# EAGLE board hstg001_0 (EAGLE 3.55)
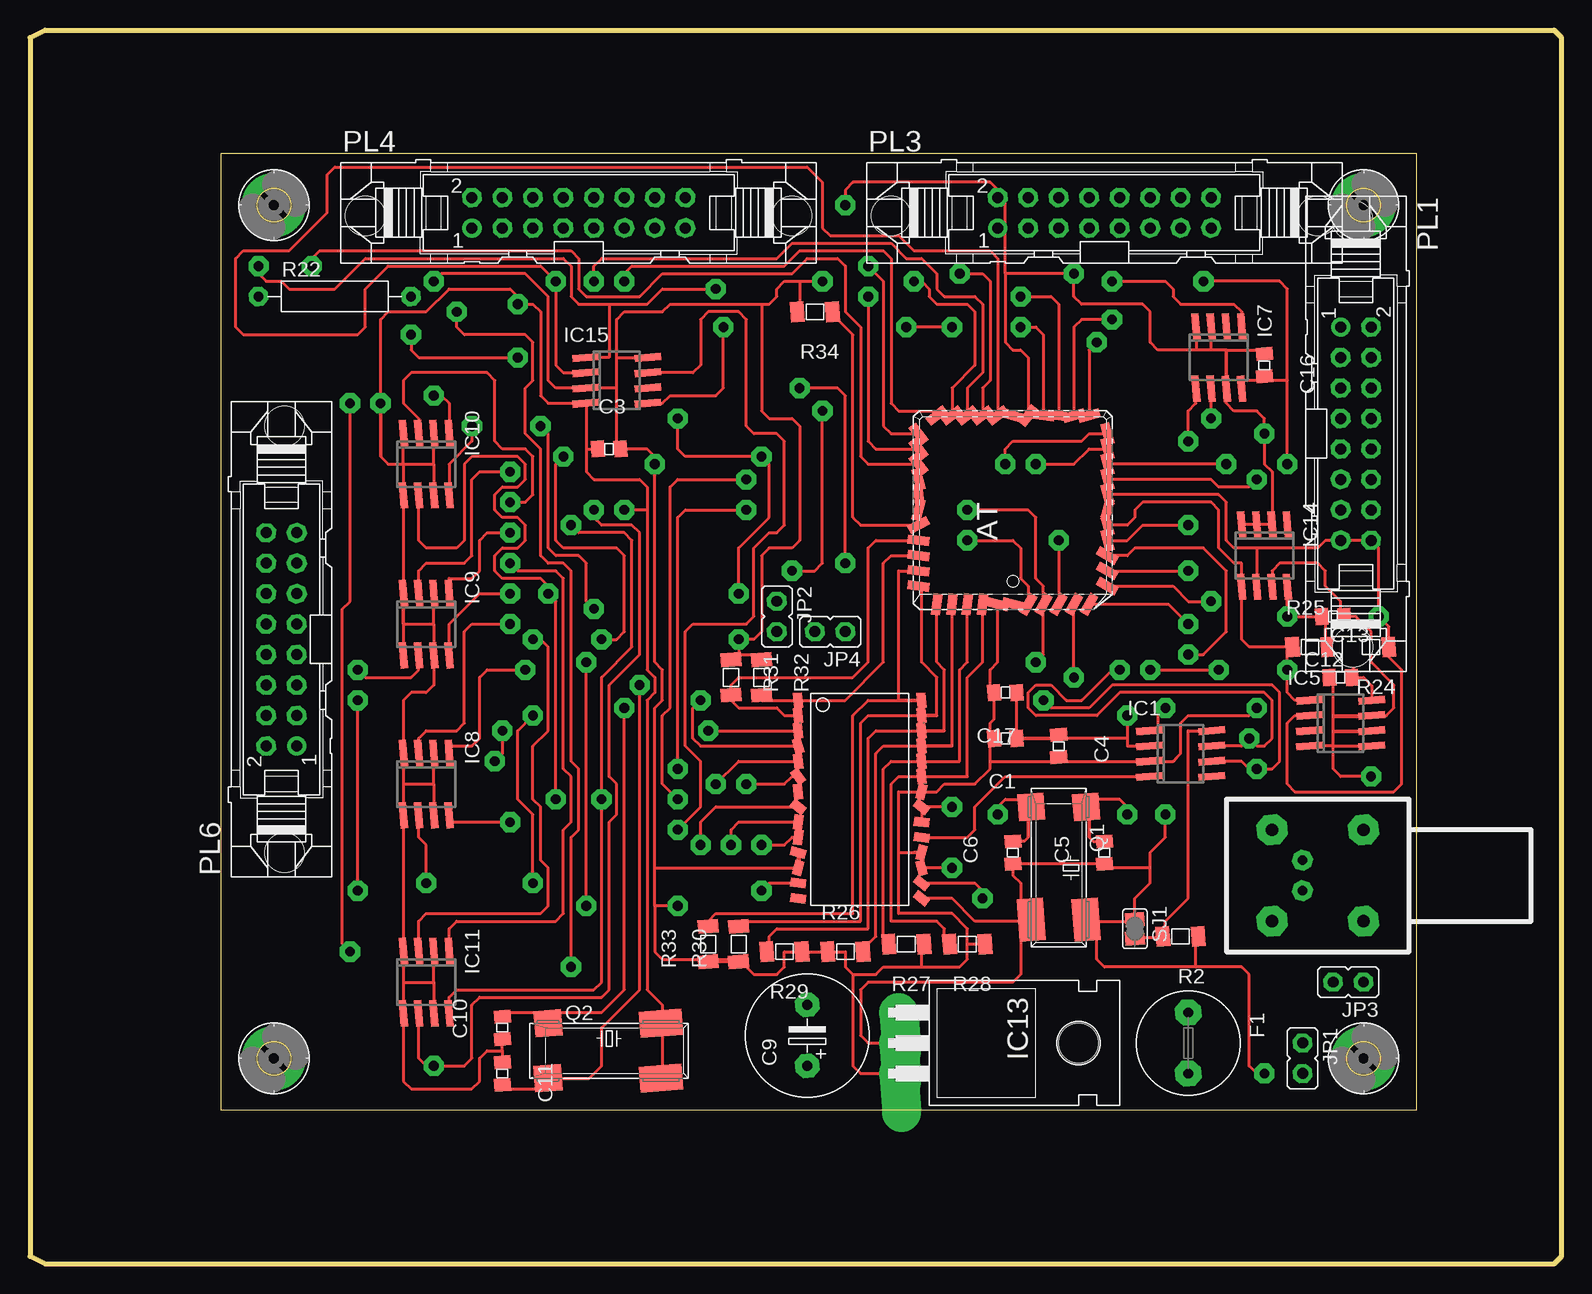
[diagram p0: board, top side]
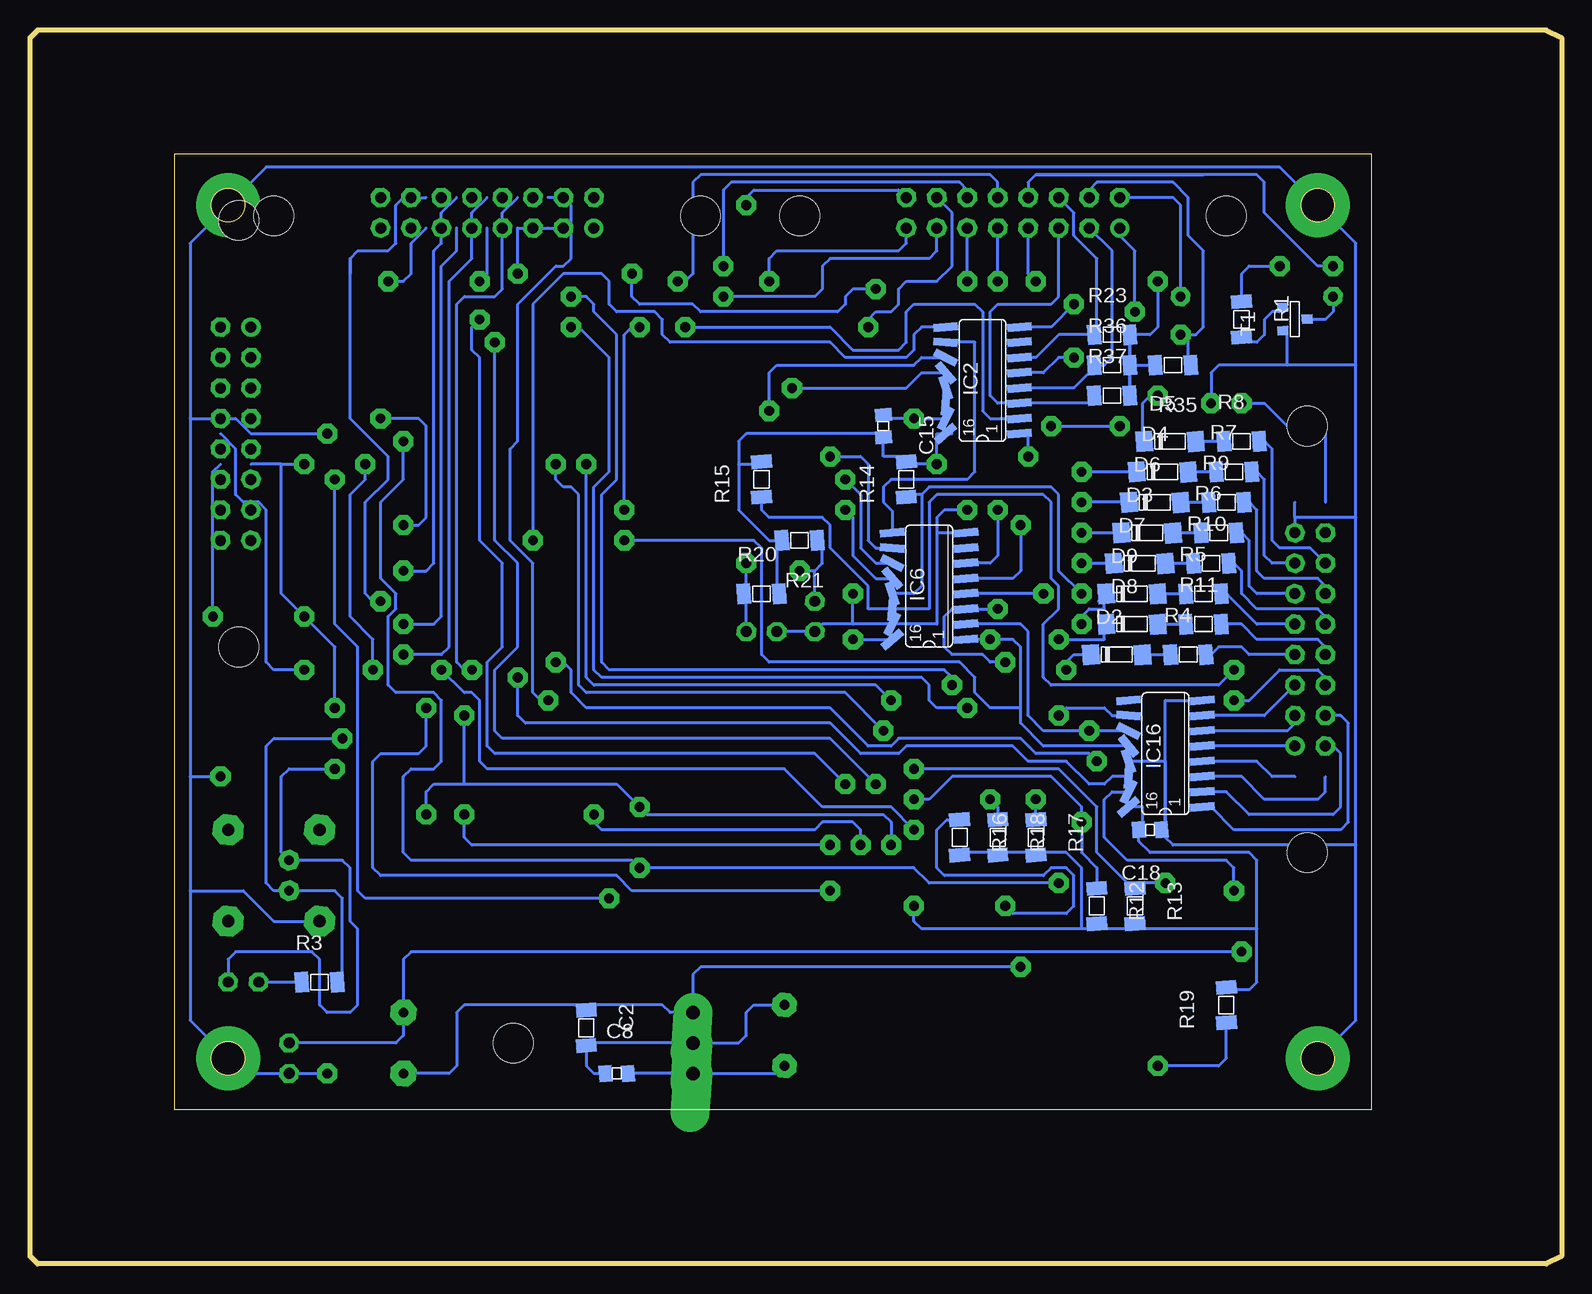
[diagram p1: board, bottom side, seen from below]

Size 127.64 x 102.87 mm. Coordinates in mm from the lower left corner, seen from the top.
Outline: 115.56,12.86 115.56,92.55 15.88,92.55 15.88,12.86 115.56,12.86
Outline: 0,0.63 1.27,0 127,0 127.64,0.63 127.64,102.23 127,102.87 1.27,102.87 0,102.23 0,0.63
Copper layers used: Top, Bottom
vRestrict: area 69.9,50.8 to 94,74.9

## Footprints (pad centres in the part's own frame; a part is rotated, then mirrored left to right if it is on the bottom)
05 = smd 1.092 x 1.397 rotated 4.4:  0.94,0 | smd 1.092 x 1.397 rotated 4.3:  -0.94,0
06 = smd 1.143 x 1.702 rotated 4.4:  1.473,0 | smd 1.143 x 1.702 rotated 4.3:  -1.473,0
-5 = drill 0.813 pad 2.007 octagon:  -2.54,0;  2.54,0
D-80 = smd 1.397 x 1.702 rotated 4.4:  -2.388,0 | smd 1.397 x 1.702 rotated 4.3:  1.905,-0.025
5 = drill 0.813 pad 2.159 octagon:  -2.54,0;  2.54,0
8 = smd 0.6 x 2.2 rotated 4.4:  -0.635,-2.6 | smd 0.6 x 2.2 rotated 4.8:  -0.635,2.6 | smd 0.6 x 2.2 rotated 4.3:  -1.905,-2.6 | smd 0.6 x 2.2 rotated 4.5:  0.635,-2.6 | smd 0.6 x 2.2 rotated 4.6:  1.905,-2.6 | smd 0.6 x 2.2 rotated 4.9:  -1.905,2.6 | smd 0.6 x 2.2 rotated 4.7:  0.635,2.6;  1.905,2.6
16 = smd 0.66 x 2.032 rotated 4.3:  -4.445,-3.073;  3.175,3.073 | smd 0.66 x 2.032 rotated 139.3:  -4.445,3.073 | smd 0.66 x 2.032 rotated 4.4:  -3.175,-3.073 | smd 0.66 x 2.032 rotated 4.5:  -1.905,-3.073 | smd 0.66 x 2.032 rotated 116.8:  -3.175,3.073 | smd 0.66 x 2.032 rotated 94.3:  -1.905,3.073 | smd 0.66 x 2.032 rotated 4.6:  -0.635,-3.073 | smd 0.66 x 2.032 rotated 71.8:  -0.635,3.073 | smd 0.66 x 2.032 rotated 4.7:  0.635,-3.073;  1.905,-3.073 | smd 0.66 x 2.032 rotated 49.3:  0.635,3.073 | smd 0.66 x 2.032 rotated 4.8:  3.175,-3.073 | smd 0.66 x 2.032 rotated 26.8:  1.905,3.073 | smd 0.66 x 2.032 rotated 4.9:  4.445,-3.073 | smd 0.66 x 2.032 rotated 5:  4.445,3.073
CC-44 = smd 0.76 x 1.8 rotated 74.5: 0 -1.27,-7.86; 1 1.27,-7.86; 2 2.54,-7.86; 3 3.81,-7.86; 4 5.08,-7.86; 5 6.35,-7.86; N 2.54,7.86 | smd 1.8 x 0.76 rotated 29.5: 0 -7.86,-1.27; 1 -7.86,-2.54; 2 -7.86,-3.81; 3 -7.86,-5.08; 4 -7.86,-6.35 | smd 1.8 x 0.76 rotated 7: 0 -7.86,2.54; 1 -7.86,3.81; 2 -7.86,5.08; 3 -7.86,6.35 | smd 1.8 x 0.76 rotated 52: 0 7.86,1.27; 1 7.86,2.54; 2 7.86,3.81; 3 7.86,5.08; 4 7.86,6.35 | smd 0.76 x 1.8 rotated 7: 4 -6.35,7.86; 5 -5.08,7.86; 6 -3.81,7.86; 7 -2.54,7.86 | smd 0.76 x 1.8 rotated 52: 5 6.35,7.86; 6 5.08,7.86; 7 3.81,7.86 | smd 0.76 x 1.8 rotated 29.5: 5 -6.35,-7.86; 6 -5.08,-7.86; 7 -3.81,-7.86 | smd 1.8 x 0.76 rotated 74.5: 6 7.86,-6.35; 7 7.86,-5.08 | smd 0.76 x 1.8 rotated 275.7: /PR 1.27,7.86 | smd 1.8 x 0.76 rotated 97.7: L1 7.86,-2.54; L2 7.86,-3.81 | smd 0.76 x 1.8 rotated 28.6: VPP -1.27,7.86 | smd 0.76 x 1.8 rotated 74.7:  -2.54,-7.86 | smd 0.76 x 1.8 rotated 74.4:  0,-7.86;  0,7.86 | smd 1.8 x 0.76 rotated 74.4:  -7.86,0;  7.86,0 | smd 1.8 x 0.76 rotated 75.1:  -7.86,1.27 | smd 1.8 x 0.76 rotated 321.2:  7.86,-1.27
-28L = smd 0.762 x 1.27 rotated 321.2: 1 1.27,-5.207; 2 1.27,5.08; 3 8.89,5.08 | smd 0.762 x 1.27 rotated 75.1: 1 0,5.08; 2 5.08,5.08; 3 6.35,-5.207 | smd 0.762 x 1.27 rotated 74.7: / 6.35,5.08 | smd 0.762 x 1.27 rotated 321.4: / 7.62,5.08 | smd 0.762 x 1.27 rotated 275.7: /AS -5.08,-5.207 | smd 0.762 x 1.27 rotated 97.2: E -2.54,-5.207 | smd 0.762 x 1.27 rotated 344.3: E 5.08,-5.207 | smd 0.762 x 1.27 rotated 97.7: L1 2.54,-5.207; L2 3.81,-5.207 | smd 0.762 x 1.27 rotated 275.9: OUT 0,-5.207 | smd 0.762 x 1.27 rotated 95.7:  -7.62,-5.207;  -6.35,-5.207;  -1.27,5.08;  -2.54,5.08;  -3.81,5.08;  -5.08,5.08;  -6.35,5.08;  -7.62,5.08 | smd 0.762 x 1.27 rotated 73.4:  -3.81,-5.207 | smd 0.762 x 1.27 rotated 52.6:  -1.27,-5.207 | smd 0.762 x 1.27 rotated 187.2:  2.54,5.08;  3.81,5.08 | smd 0.762 x 1.27 rotated 187.4:  8.89,-5.207;  7.62,-5.207
220H = drill 1.118 pad 3.251 offset:  -2.54,-10.16;  0,-10.16;  2.54,-10.16 | hole 3.302: 0,4.826
1 = drill 0.914 pad 1.6 octagon:  0,-1.27;  0,1.27
2,8-P = drill 2.794 pad 5.334 round: 8 0,0
V = drill 0.914 pad 1.6 round:  -8.89,-1.27 | drill 0.914 pad 1.6 octagon:  -8.89,1.27;  -6.35,-1.27;  -6.35,1.27;  -3.81,-1.27;  -3.81,1.27;  -1.27,-1.27;  -1.27,1.27;  1.27,-1.27;  1.27,1.27;  3.81,-1.27;  3.81,1.27;  6.35,-1.27;  6.35,1.27;  8.89,-1.27;  8.89,1.27 | hole 3.302: 17.78,-0.254; -17.78,-0.254
N_EPL = drill 1.016 pad 2.54 octagon: 1 -3.81,3.81; 2 3.81,3.81; 3 -3.81,-3.81; 4 3.81,-3.81 | drill 0.813 pad 1.676 octagon: H -1.27,1.27; L 1.27,1.27
SMX = smd 3.556 x 2.184 rotated 4.4:  4.318,-2.286 | smd 3.556 x 2.184 rotated 4.5:  4.318,2.286 | smd 2.286 x 2.184 rotated 4.3:  -5.08,-2.286 | smd 2.286 x 2.184 rotated 4.6:  -5.08,2.286
12,5 = drill 0.813 pad 1.6 octagon:  -6.35,0;  6.35,0
 = smd 1.168 x 1.6 rotated 4.3:  -0.762,0 | smd 1.168 x 1.6 rotated 4.4:  0.762,0
T-23 = smd 0.787 x 0.889 rotated 4.4:  0.991,1.016 | smd 0.787 x 0.889 rotated 4.3:  -0.94,1.016 | smd 0.787 x 0.889 rotated 4.5:  0.025,-1.016

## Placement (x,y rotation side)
C1  100n  [05]  81.28,43.81 180 top
C2  330n  [06]  81.28,19.68 270 bottom
C3  100n  [05]  48.26,67.94 0 top
C4  100n  [05]  85.72,43.18 270 top
C5  15pF  [05]  89.53,34.29 90 top
C6  15pF  [05]  81.92,34.29 90 top
C8  100n  [05]  78.74,15.88 0 bottom
C9  Elko 470uF  [-5]  64.77,19.05 90 top
C10  30pF +-10pF  [05]  39.37,19.68 90 top
C11  30 pF+-10pF  [05]  39.37,15.88 270 top
C12  100n  [05]  108.58,53.97 180 top
C13  100n  [05]  109.22,48.89 0 top
C15  100n  [05]  56.52,69.85 270 bottom
C16  100n  [05]  102.87,74.93 270 top
C17  100n  [05]  81.28,47.62 180 top
C18  100n  [05]  34.29,36.2 180 bottom
D2  SMD4148  [D-80]  36.83,50.8 0 bottom
D3  SMD4148  [D-80]  34.29,60.96 0 bottom
D4  SMD4148  [D-80]  33.02,66.04 0 bottom
D5  SMD4148  [D-80]  32.39,68.58 0 bottom
D6  SMD4148  [D-80]  33.66,63.5 0 bottom
D7  SMD4148  [D-80]  34.92,58.42 0 bottom
D8  SMD4148  [D-80]  35.56,53.34 0 bottom
D9  SMD4148  [D-80]  35.56,55.88 0 bottom
F1  T200mA  [5]  96.52,18.41 270 top
IC1  PCA82C250  [8]  95.89,42.55 270 top
IC2  74165  [16]  48.26,73.66 90 bottom
IC3  AT89S53  [CC-44]  81.92,62.86 90 top
IC4  SJA1000  [-28L]  69.22,39.37 270 top
IC5  DS1621  [8]  109.22,45.08 270 top
IC6  74165  [16]  52.7,56.52 90 bottom
IC7  MAX700  [8]  99.06,75.56 180 top
IC8  ILD213T  [8]  33.02,40 180 top
IC9  ILD213T  [8]  33.02,53.34 180 top
IC10  ILD213T  [8]  33.02,66.67 180 top
IC11  ILD213T  [8]  33.02,23.49 180 top
IC13  78S05  [220H]  82.55,18.41 270 top
IC14  X24C04  [8]  102.87,59.05 180 top
IC15  DS1804  [8]  48.9,73.66 270 top
IC16  74HC595  [16]  33.02,42.55 90 bottom
JP1  2-polig  [1]  106.05,17.14 180 top
JP2  JP1E  [1]  62.23,53.97 180 top
JP3  2-polig  [1]  109.86,23.49 90 top
JP4  JP1E  [1]  66.67,52.7 90 top
PAD1  BO2,8P  [2,8-P]  20.32,88.27 0 top
PAD2  BO2,8P  [2,8-P]  20.32,17.14 0 top
PAD3  BO2,8P  [2,8-P]  111.12,17.14 0 top
PAD4  BO2,8P  [2,8-P]  111.12,88.27 0 top
PL1  06V  [V]  110.49,69.22 270 top
PL2  CAN_BUS  [N_EPL]  107.31,32.38 90 top
PL3  10V  [V]  89.53,87.63 0 top
PL4  16V  [V]  45.72,87.63 0 top
PL6  20V  [V]  20.95,52.07 90 top
Q1  16MHZ  [SMX]  85.72,33.02 270 top
Q2  16MHZ  [SMX]  48.26,17.78 0 top
R1  4k7  [06]  26.67,78.74 270 bottom
R2  47k  [06]  95.89,27.3 180 top
R3  120R  [06]  103.5,23.49 0 bottom
R4  2k7  [06]  31.12,50.8 0 bottom
R5  2k7  [06]  29.84,55.88 0 bottom
R6  2k7  [06]  28.57,60.96 0 bottom
R7  2k7  [06]  27.3,66.04 0 bottom
R8  2k7  [06]  26.67,68.58 0 bottom
R9  2k7  [06]  27.94,63.5 0 bottom
R10  2k7  [06]  29.21,58.42 0 bottom
R11  2k7  [06]  29.84,53.34 0 bottom
R12  4k7  [06]  38.73,29.84 270 bottom
R13  4k7  [06]  35.56,29.84 270 bottom
R14  4k7  [06]  54.61,65.41 90 bottom
R15  4k7  [06]  66.67,65.41 90 bottom
R16  4k7  [06]  50.16,35.56 270 bottom
R17  4k7  [06]  43.81,35.56 270 bottom
R18  4k7  [06]  46.99,35.56 270 bottom
R19  4k7  [06]  27.94,21.59 90 bottom
R20  10k  [06]  66.67,55.88 0 bottom
R21  10k  [06]  63.5,60.33 180 bottom
R22  100 Ohm  [12,5]  25.4,80.64 0 top
R23  10 k  [06]  37.47,77.47 0 bottom
R24  1k  [06]  111.76,51.44 180 top
R25  1k  [06]  106.68,51.44 0 top
R26  4k7  [06]  67.94,26.04 0 top
R27  4k7  [06]  73.03,26.67 180 top
R28  4k7  [06]  78.1,26.67 180 top
R29  4k7  [06]  62.87,26.04 180 top
R30  4k7  [06]  59.05,26.67 90 top
R31  4k7  [06]  58.42,48.89 270 top
R32  4k7  [06]  60.96,48.89 270 top
R33  4k7  [06]  56.52,26.67 90 top
R34  4k7  [06]  65.41,79.38 180 top
R35  10 k  [06]  32.39,74.93 180 bottom
R36  10 k  [06]  37.47,74.93 0 bottom
R37  10 k  [06]  37.47,72.39 0 bottom
SJ1  SJ  []  92.08,27.94 270 top
T1  BC818  [T-23]  22.23,78.74 90 bottom

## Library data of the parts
C1-C6 C8 C10-C13 C15-C18 D2-D9 R1-R21 R23-R37 T1 = smd
C9 R22 = discrete
F1 = fuse
IC1 IC3-IC5 IC7-IC11 IC14 IC15 PL2 = andit4at
IC2 IC6 IC16 = andi74sm
IC13 = linear
JP1-JP4 = jumps
PAD1-PAD4 = holes
PL1 PL3 PL4 PL6 = pinh-v
Q1 Q2 = quartz
SJ1 = jumper

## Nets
+5V: C1. C3. C4. C8. C9. C12. C13. C15. C16. C17. C18. IC1. IC2. IC3. IC4.1 IC4.2 IC4.3 IC4.E IC5. IC6. IC7. IC13. IC14. IC15. IC16. PL1. PL3. PL4. R12. R13. R14. R15. R16. R17. R18. R19. R20. R21. R23. R24. R25. R26. R27. R28. R29. R30. R31. R32. R33. R34. R35. R36. R37.
GND: C1. C2. C3. C4. C5. C6. C8. C9. C10. C11. C12. C13. C15. C16. C17. C18. IC1. IC2. IC3. IC4. IC4.1 IC4.2 IC4.3 IC5. IC6. IC7. IC8. IC9. IC10. IC11. IC13. IC14. IC15. IC16. JP1. JP2. JP4. PAD1.8 PAD2.8 PAD3.8 PAD4.8 PL1. PL2.1 PL3. PL4. PL6. Q1. Q2. R2. SJ1. T1.
N$1: IC3.0 IC4. R28.
N$2: IC3.1 IC4. R27.
N$3: IC3.5 IC4. R33.
N$4: IC3.VPP R34.
N$5: IC3.7 IC4. R31.
N$6: PL4. R22.
N$9: IC1. IC4.
N$10: IC2. IC3.1 IC6. IC16.
N$11: C11. IC3.L2 Q2.
N$12: IC2. IC3.2
N$13: IC3.0 IC15. PL4.
N$15: IC16. PL6.
N$16: IC1. PL2.H PL3. R3.
N$17: IC15. PL4.
N$18: PL6. R11.
N$19: IC2. PL4. R35.
N$20: IC2. PL4. R37.
N$21: PL6. R10.
N$22: IC2. PL4. R36.
N$23: C2. F1. IC13. PL4.
N$24: IC2. IC6.
N$26: PL6. R9.
N$27: D9. R5.
N$28: D2. R4.
N$29: IC2. IC3.0 IC6. IC16.
N$31: D3. R6.
N$32: D4. R7.
N$33: D5. R8.
N$35: D6. R9.
N$36: IC1. JP3. PL2.L PL3.
N$37: IC3.4 IC4./AS
N$38: IC3.6 PL3.
N$39: IC3.5 PL3.
N$40: IC3.7 PL3.
N$41: IC3. IC7.
N$42: IC3.5 IC4.
N$43: IC16. PL6.
N$44: IC3.1 IC5. IC14. PL1. R24.
N$45: IC3.0 IC5. IC14. PL1. R25.
N$46: IC3.6 IC4.E
N$47: IC3.7 IC4.
N$48: IC3.2 IC4./
N$49: IC7. PL3.
N$50: IC4./ IC7. IC16.
N$51: C5. IC4.L2 Q1.
N$52: C6. IC4.L1 Q1.
N$53: R22. T1.
N$54: IC3.2 PL4.
N$55: IC1. IC4.
N$56: IC3.3 PL4.
N$57: IC3.5 PL4.
N$58: IC3.6 PL4.
N$59: IC3.4 PL4.
N$60: IC3.7 R1.
N$61: F1. JP1. PL6.
N$63: IC1. R2. SJ1.
N$64: D7. R10.
N$65: JP3. R3.
N$67: D8. R11.
N$68: D9. IC8.
N$70: C10. IC3.L1 Q2.
N$71: D3. IC9.
N$72: D4. IC9.
N$73: D5. IC10.
N$74: D6. IC10.
N$75: D7. IC11.
N$76: IC6. IC8. R12.
N$77: D8. IC11.
N$78: IC2. PL4. R23.
N$79: IC3.4 PL3.
N$80: IC6. IC8. R13.
N$81: R1. T1.
N$82: D2. IC8.
N$83: IC6. IC9. R14.
N$85: IC6. IC9. R15.
N$87: IC6. IC10. R16.
N$89: IC6. IC10. R17.
N$90: IC16. PL6.
N$91: IC6. IC11. R18.
N$92: IC16. PL6.
N$93: IC6. IC11. R19.
N$94: IC16. PL6.
N$95: IC16. PL6.
N$96: IC3.3 IC15.
N$97: IC16. PL6.
N$98: IC3.3 IC16.
N$99: IC16. PL6.
N$100: IC2. JP4. R20.
N$101: IC2. JP2. R21.
N$102: IC3.2 IC4. R26.
N$104: IC3.3 IC4. R29.
N$105: IC3.4 IC4. R30.
N$106: IC3.6 IC4. R32.
N$107: IC3.1 IC15. PL4.
N$108: PL6. R8.
N$109: PL6. R4.
N$110: PL6. R5.
N$111: PL6. R6.
N$112: PL6. R7.

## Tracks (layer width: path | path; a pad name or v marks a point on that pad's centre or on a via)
+5V  (via drill 0.81 pad 1.68)
  Top 0.254: v97.79,81.92 104.14,81.92 104.78,81.28 104.78,73.66 | 73.66,34.29 74.3,34.29 72.39,34.29 | 64.13,33.15 IC4.3 | 64.13,33.15 64.13,34.29 | 72.39,34.29 72.39,39.37 IC4.1 75.56,39.37 76.2,40 78.74,40 80.01,41.27 80.01,41.91 | 72.39,34.29 72.39,29.21 76.84,29.21 78.1,27.94 78.1,26.67 | IC4.E 64.01,33.15 64.13,33.02 | 52.07,33.02 64.13,33.02 | 80.64,55 80.64,50.17 80.01,49.53 80.01,47.62 80.34,47.62 80.34,45.42 80.01,45.08 80.01,43.81 | 102.87,74.3 102.87,73.99 102.87,73.66 | 64.13,33.02 64.13,33.15 | 110.49,48.89 110.29,49.1 110.29,51.44 108.15,51.44 107.95,51.44 107.95,53.97 107.64,53.97 v104.78,53.97 104.78,56.45 | 111.82,46.99 111.82,48.2 111.12,48.89 110.49,48.89 | 110.49,48.89 110.16,48.89 | v104.78,66.67 104.78,73.66 | 104.78,73.66 102.87,73.66 | 100.97,72.97 100.97,73.66 102.87,73.66 | 95.25,41.91 95.56,42.22 | 85.72,41.91 93.28,41.91 95.25,41.91 | 95.25,41.91 95.89,42.55 95.89,45.08 96.52,45.72 101.6,45.72 v102.23,46.36 | 78.1,26.67 R28. | R26. 66.04,26.04 | R26. 67.94,26.04 67.94,24.77 68.58,24.13 | R26. R29. 62.87,26.04 62.87,24.77 62.23,24.13 60.33,24.13 59.69,24.77 | R33. 58.85,25.2 59.05,25.4 R30. 59.26,25.2 59.69,24.77 | 80.01,43.81 80.34,43.81 | 80.01,41.91 80.01,43.81 | 85.72,41.91 85.72,42.24 | 80.01,41.91 85.72,41.91 | 59.69,24.77 59.69,25.4 52.7,25.4 52.07,26.04 52.07,29.84 | 52.07,29.84 52.07,33.02 | 68.58,24.13 68.58,16.51 69.22,15.88 IC13. | 68.58,24.13 70.48,24.13 71.12,24.77 74.3,24.77 | 74.93,26.67 R27. 74.3,26.67 74.3,24.77 | 74.3,24.77 77.47,24.77 78.1,25.4 78.1,26.67 | 48.9,73.03 46.3,73.03 43.81,73.03 43.18,73.66 43.18,80.64 41.27,82.55 34.29,82.55 v33.66,81.92
  Top 0.254: 48.9,73.03 48.9,75.56 | 48.9,75.56 51.49,75.56 | 48.9,75.56 48.9,78.74 49.53,79.38 52.7,79.38 53.34,80.01 60.96,80.01 | 52.07,33.02 52.07,46.36 52.7,46.99 52.7,49.53 52.07,50.17 v52.07,66.67 52.07,67.31 51.44,67.94 49.53,67.94 | R31. 58.42,50.17 58.62,50.37 58.62,50.6 58.42,50.8 59.05,50.8 | R32. 60.96,50.17 60.33,50.8 59.05,50.8 | 64.13,81.92 62.87,81.92 62.23,81.28 62.23,80.64 61.59,80.01 60.96,80.01 | 64.13,81.92 v66.04,81.92 | 63.93,79.38 64.13,79.38 64.13,81.92 | v53.98,29.84 52.07,29.84 | 49.53,67.94 49.2,67.94 | 48.9,73.03 48.9,68.58 49.53,67.94 | 59.05,50.8 v59.05,52.07 60.33,52.07 60.96,52.7 60.96,59.05 61.59,59.69 63.5,59.69 64.13,60.33 64.13,69.85 63.5,70.48 61.59,70.48 60.96,71.12 60.96,80.01
  Bottom 0.254: 94.61,86.36 95.89,85.09 95.89,82.55 96.52,81.92 v97.79,81.92 | 106.68,66.67 109.22,66.67 | 106.68,66.67 v104.78,66.67 | 106.68,66.67 106.68,55.88 v104.78,53.97 102.23,51.44 v102.23,46.36 | 77.8,15.88 IC13. 65.41,15.88 64.77,16.51 | 36.2,38.1 36.09,38.1 34.92,38.1 34.92,36.2 35.23,36.2 35.23,35.23 34.29,34.29 26.04,34.29 25.4,33.66 25.4,27.94 | 54.61,86.36 54.61,85.09 55.24,84.45 65.41,84.45 66.04,83.82 v66.04,81.92 | 66.67,66.67 66.67,66.88 | 66.67,66.67 66.88,66.88 | 36.2,74.93 35.76,75.36 | 35.99,74.93 36.2,74.93 | 35.99,77.47 35.99,75.13 36.2,74.93 | 35.99,72.39 36.2,72.39 35.99,72.59 | 35.99,72.59 35.99,74.93 | 33.66,74.93 33.86,74.93 35.99,74.93 | 35.99,72.59 35.99,77.04 35.56,77.47 34.29,77.47 33.66,78.11 v33.66,81.92 | 50.8,69.22 51.33,69.22 52.07,69.22 v52.07,66.67 54.61,66.67 54.61,66.88 54.61,67.31 56.52,67.31 | 68.58,66.67 66.67,66.67 | 64.77,60.33 64.97,60.33 65.41,60.33 | 56.52,67.31 56.52,68.91 | 40,27.94 53.34,27.94 53.98,28.57 v53.98,29.84 | 40,27.94 40,33.02 41.27,34.29 43.81,34.29 | 35.56,27.94 35.56,28.37 | 35.56,27.94 38.73,27.94 | 38.73,27.94 38.73,28.37 | 38.73,27.94 40,27.94 | 65.2,55.88 65.41,55.88 65.41,60.33 | 65.41,60.33 66.04,60.33 68.58,62.86 68.58,66.67 | 68.58,66.67 68.58,68.58 67.94,69.22 56.52,69.22 56.52,67.31 | 25.4,27.94 35.56,27.94 | 25.4,27.94 25.4,23.49 26.04,22.86 27.94,22.86 27.94,23.06 | 43.81,34.29 43.81,34.09 | 43.81,34.29 46.99,34.29 | 46.99,33.66 46.99,34.09 46.99,34.29 | 50.16,34.09 50.16,34.29 46.99,34.29 | v59.05,52.07 55.78,52.07 v59.05,52.07
GND  (via drill 0.81 pad 1.68)
  Top 0.254: 97.16,78.17 97.22,78.11 97.22,76.26 97.16,76.2 | 99.69,76.2 102.54,76.2 | 99.69,76.2 98.42,76.2 | 99.69,76.2 99.69,72.97 | 97.16,76.2 93.98,76.2 93.34,76.84 93.34,79.38 92.71,80.01 87.63,80.01 87,80.64 v87,82.55 81.28,82.55 | 83.19,70.72 83.19,75.56 82.55,76.2 81.92,76.2 81.28,76.84 81.28,82.55 | 111.76,44.45 111.82,44.39 108.64,44.39 108.58,44.45 | 111.76,45.72 111.82,45.66 108.64,45.66 108.58,45.72 | 111.76,43.18 111.82,43.24 | 108.58,43.18 106.62,43.18 | 108.58,45.72 111.76,45.72 | C13. 107.95,48.89 108.58,48.26 108.58,45.72 | 100.97,61.66 102.17,61.66 102.23,61.59 102.23,61.66 103.44,61.66 103.5,61.59 | 111.76,45.72 111.82,45.72 | 111.76,45.72 113.03,45.72 113.67,46.36 113.67,48.26 111.76,50.17 111.76,52.7 110.49,53.97 C12. 109.22,53.97 109.22,55.25 107.95,56.52 107.95,57.78 107.31,58.42 104.14,58.42 103.5,57.78 103.5,56.45 | IC4.2 v76.84,38.1 IC4.2 | 99.69,76.2 102.87,76.2 C16. 102.87,75.56 | 99.69,76.2 99.69,71.75 100.33,71.12 102.23,71.12 102.87,70.48 v102.87,69.22 102.87,66.67 103.5,66.04 103.5,61.59 | 103.5,61.59 103.5,61.66 | 98.42,76.2 97.16,76.2 | 98.42,76.2 98.42,78.17 | 108.58,44.45 108.58,45.72 | 111.76,44.45 111.82,44.45 | 108.58,44.45 111.76,44.45 | 108.58,43.18 108.58,44.45 | 111.76,43.18 IC5. | 108.58,43.18 111.76,43.18 | 108.58,43.18 108.58,41.27 109.22,40.64 v111.76,40.64 | 89.53,33.02 C5. | 89.53,33.02 89.2,33.35 C6. 81.92,32.38 82.55,31.75 82.55,28.57 | 89.53,33.66 89.84,33.35 | 89.53,33.66 89.53,33.02 | v94.61,37.47 94.61,35.56 93.34,34.29 93.34,33.02 | 93.34,33.02 90.17,33.02 89.53,33.66 | 93.34,33.02 93.34,31.75 92.08,30.48 92.08,28.7 92.08,28.57 88.9,28.57
  Top 0.254: 88.9,28.57 88.9,25.4 89.53,24.77 97.16,24.77 | R2. 97.16,27.3 97.16,24.77 | 91.44,43.81 C1. | C4. 85.72,44.45 85.09,43.81 C1. | 93.28,43.18 91.44,43.18 91.44,43.81 | 31.12,66.67 31.12,69.28 | 31.12,66.67 IC10. | 29.84,66.67 31.12,66.67 | v29.21,71.75 29.21,67.31 | 31.12,53.34 31.12,55.94 | 33.66,53.34 33.66,50.74 | 33.66,66.67 33.66,64.08 | 31.12,66.67 33.66,66.67 | 31.12,66.67 31.12,53.34 | 33.66,53.34 33.66,55.94 | v91.44,45.72 91.44,43.81 | 97.16,24.77 100.97,24.77 101.6,24.13 101.6,16.51 102.23,15.88 v102.87,15.88 | 74.3,30.48 76.84,30.48 78.74,28.57 82.55,28.57 | 82.55,28.57 82.55,24.13 81.92,23.49 69.85,23.49 69.22,22.86 69.22,19.05 69.85,18.41 72.39,18.41 | 46.36,71.75 46.3,71.75 43.18,71.75 | v67.94,88.27 67.94,89.53 68.58,90.17 80.01,90.17 81.28,88.9 81.28,82.55 | 33.66,53.34 33.66,48.26 33.02,47.62 31.75,47.62 31.12,46.99 31.12,42.55 | 31.12,53.34 33.66,53.34 | 31.12,53.34 IC9. | C17. 81.92,47.62 82.22,47.32 C1. | IC4.2 74.3,36.83 | IC4.2 74.3,36.83 | IC4.2 74.3,36.83 | 83.44,28.7 83.31,28.7 83.19,28.57 82.55,28.57 | 88.01,28.7 88.14,28.7 88.27,28.57 88.9,28.57 | 64.01,38.1 57.15,38.1 55.88,36.83 v55.88,34.92 | 31.12,42.55 31.12,40 | 31.12,42.55 31.12,42.61 | 33.66,40 33.66,42.61 | 31.12,40 31.12,37.47 | 31.12,37.47 IC8. | 31.12,40 33.66,40 | 31.12,26.04 31.12,26.09 | 31.12,23.49 31.12,20.95 | 33.66,23.49 33.66,20.89 | 33.66,23.49 33.66,26.09 | 31.12,23.49 33.66,23.49 | 31.12,26.04 31.12,23.49 | 31.12,37.47 31.12,26.04 | 33.66,40 33.66,37.41 33.66,36.83 | 43.18,71.75 42.55,72.39 42.55,79.38 41.91,80.01 v40.64,80.01 40.64,80.64 40,81.28 34.92,81.28 33.02,79.38 29.84,79.38 29.21,78.74 29.21,67.31 | 43.18,71.75 46.36,71.75
  Top 0.254: 31.12,20.95 IC11. | 31.12,20.95 31.12,15.24 31.75,14.6 36.83,14.6 37.47,15.24 37.47,17.14 38.1,17.78 39.37,17.78 | v59.05,55.88 59.05,59.69 61.59,62.23 61.59,66.67 v60.96,67.31 54.61,67.31 53.98,67.94 v53.98,70.48 | 52.7,19.68 52.7,20.32 52.58,20.19 52.58,20.07 52.58,19.81 52.7,19.68 | 52.7,19.68 52.7,21.59 51.44,22.86 51.44,46.99 52.07,47.62 52.07,48.89 51.44,49.53 51.44,62.86 | 39.37,16.51 C11. 39.37,17.78 | 39.37,17.78 C10. | 52.58,15.49 52.58,15.37 52.7,15.24 52.7,19.68 | 46.36,71.75 46.36,67.94 | 46.36,67.94 46.36,66.04 46.99,65.41 50.8,65.41 51.44,64.77 51.44,62.86 | 46.36,67.94 C3. | 33.66,66.67 33.66,69.28 | 29.84,66.67 33.66,66.67 | 29.21,67.31 29.84,66.67 | 51.44,62.86 v49.53,62.86
  Bottom 0.254: 114.3,70.48 114.3,85.09 PAD4.8 107.95,91.44 23.5,91.44 PAD1.8 17.14,85.09 17.14,74.93 | 114.3,70.48 114.3,40.64 | 114.3,40.64 114.3,31.11 | 114.3,31.11 114.3,20.32 PAD3.8 109.86,15.88 JP1. v102.87,15.88 | PAD2.8 17.14,20.32 17.14,34.92 | 83.82,86.36 84.45,86.36 87,86.36 v87,82.55 | PL2.1 107.31,28.57 109.86,31.11 114.3,31.11 | 114.3,40.64 v111.76,40.64 | 109.22,69.22 v102.87,69.22 109.22,69.22 | 91.44,40 78.74,40 v76.84,38.1 76.2,37.47 56.52,37.47 55.88,36.83 v55.88,34.92 | v94.61,37.47 94.61,39.37 93.98,40 91.44,40 | C8. 80.64,15.88 81.28,16.51 81.28,18.21 81.28,18.41 72.39,18.41 68.58,18.41 67.94,19.05 67.94,20.95 67.31,21.59 C9. | 22.23,62.23 22.23,60.96 | 33.02,41.91 33.02,46.99 29.95,46.99 | 36.2,41.91 36.09,41.91 33.02,41.91 | JP4. JP2. 61.59,53.34 59.05,53.34 | 49.53,60.96 49.63,60.96 52.07,60.96 | 91.44,40 v91.44,45.72 | 52.07,60.96 52.07,53.34 55.78,53.34 59.05,53.34 | 44.45,78.11 45.19,78.11 42.55,78.11 v40.64,80.01 | PL4. 55.24,89.53 67.31,89.53 67.94,88.9 v67.94,88.27 | 109.22,69.22 110.49,70.48 114.3,70.48 | 51.33,70.48 v53.98,70.48 56.52,70.48 C15. | v29.21,71.75 29.21,74.3 28.57,74.93 22.86,74.93 | 17.14,34.92 17.14,62.23 | 17.14,62.23 17.14,74.93 | 23.24,77.8 23.16,77.8 22.86,78.11 22.86,74.93 | 33.66,36.2 C18. 33.02,36.2 33.02,41.91 | 33.02,41.91 33.02,35.56 32.39,34.92 17.14,34.92 | 17.14,74.93 22.86,74.93 | 22.23,62.23 22.23,63.5 | 17.14,62.23 22.23,62.23 | 55.78,59.69 57.15,59.69 57.78,60.33 57.78,66.67 58.42,67.31 v60.96,67.31 | 59.05,53.34 v59.05,55.88 | 52.07,60.96 52.07,62.23 51.44,62.86 v49.53,62.86
N$1
  Top 0.254: 79.38,55 79.38,50.17 78.1,48.89 78.1,40.64 74.3,40.64 72.39,40.64 71.75,40 71.75,28.57 75.56,28.57 76.2,27.94 76.2,26.67 | 76.2,26.67 76.84,26.04 | 76.84,26.67 76.63,26.67 76.2,26.67
N$2
  Top 0.254: 78.1,55 78.1,50.17 77.47,49.53 77.47,41.91 74.3,41.91 71.75,41.91 71.12,41.27 71.12,26.67 71.55,26.67 71.75,26.67
N$3
  Top 0.254: 74.06,57.78 72.39,57.78 72.39,46.99 IC4. 69.85,46.99 68.58,45.72 68.58,29.21 57.15,29.21 56.52,28.57 56.52,28.14
N$4
  Top 0.254: IC3.VPP 69.22,61.59 68.58,62.23 68.58,77.47 67.31,78.74 66.67,78.74 66.67,79.38 R34.
N$5
  Top 0.254: 74.06,60.33 70.48,60.33 69.85,59.69 69.85,50.17 68.58,48.89 59.05,48.89 58.42,48.26 58.42,47.42 58.42,46.99 59.05,46.36 62.23,46.36 62.87,45.72 64.01,45.72 64.13,45.72
N$6
  Bottom 0.254: R22. 31.75,88.27 32.39,88.9 36.83,88.9
N$9  (via drill 0.81 pad 1.68)
  Top 0.254: 64.01,31.75 61.59,31.75 v60.96,31.11 | 93.28,44.45 93.98,44.45 93.98,45.72 v94.61,46.36
  Bottom 0.254: v60.96,31.11 77.47,31.11 78.74,32.38 98.42,32.38 99.06,33.02 99.06,41.91 98.42,42.55 95.25,42.55 94.61,43.18 v94.61,46.36
N$10  (via drill 0.81 pad 1.68)
  Top 0.254: v83.82,50.17 84.45,50.8 84.45,55 84.45,56.52 83.82,57.15 83.82,62.23 83.19,62.86 v78.1,62.86 | v38.73,41.91 39.37,42.55 v39.37,44.45 | v76.84,78.11 v73.03,78.11
  Bottom 0.254: v83.82,50.17 83.19,50.17 82.55,49.53 82.55,47.62 81.28,46.36 60.96,46.36 57.78,43.18 55.88,43.18 55.24,43.81 45.09,43.81 43.81,42.55 39.37,42.55 v38.73,41.91 | 36.09,44.45 v39.37,44.45 43.18,44.45 44.45,45.72 44.45,52.7 45.09,53.34 49.63,53.34 | 45.19,70.48 47.62,70.48 48.26,71.12 48.26,79.38 48.9,80.01 53.98,80.01 54.61,79.38 54.61,76.84 55.24,76.2 59.05,76.2 60.96,78.11 v73.03,78.11 | v76.84,78.11 77.47,78.11 78.1,77.47 v78.1,62.86
N$11  (via drill 0.81 pad 1.68)
  Top 0.254: IC3.L2 85.72,80.01 85.09,80.64 v82.55,80.64 | 39.37,14.93 39.37,14.6 43.18,14.6 43.18,15.49 46.61,15.49 47.62,16.51 47.62,19.68 50.8,22.86 v50.8,48.26
  Bottom 0.254: v82.55,80.64 81.28,80.64 80.64,80.01 80.64,79.38 78.74,77.47 78.74,65.41 80.01,64.14 80.01,50.17 79.38,49.53 51.44,49.53 50.8,48.89 v50.8,48.26
N$12  (via drill 0.81 pad 1.68)
  Top 0.254: v85.72,60.33 85.72,55
  Bottom 0.254: v85.72,60.33 85.72,80.01 83.19,82.55 80.01,82.55 79.38,81.92 79.38,80.01 78.74,79.38 75.56,79.38 74.93,78.74 74.93,77.47 74.3,76.84 60.96,76.84 59.69,75.56 54.61,75.56 53.98,76.2 53.98,77.47 53.34,78.11 IC2.
N$13  (via drill 0.81 pad 1.68)
  Top 0.254: 46.3,74.3 44.45,74.3 43.81,74.93 v43.81,81.92 42.55,83.19 29.84,83.19 27.94,81.28 27.94,78.11 27.3,77.47 17.78,77.47 17.14,78.11 17.14,83.82 17.78,84.45 21.59,84.45 24.77,87.63 24.77,90.81 25.4,91.44 64.77,91.44 66.04,90.17 66.04,86.36 66.67,85.73 72.39,85.73 73.66,84.45 80.01,84.45 80.64,83.82 IC3.0
  Bottom 0.254: v43.81,81.92 44.45,82.55 44.45,86.36
N$15
  Bottom 0.254: 29.95,45.72 24.77,45.72 22.23,48.26
N$16  (via drill 0.81 pad 1.68)
  Top 0.254: v90.81,49.53 90.17,49.53 87.63,46.99 86.36,46.99 85.09,48.26 83.82,48.26 83.19,47.62 83.19,46.36 83.82,45.72 88.9,45.72 90.81,47.62 102.87,47.62 103.5,46.99 103.5,43.81 102.87,43.18 102.23,43.18 v101.6,43.81 100.97,43.18 98.48,43.18 98.42,43.18
  Bottom 0.254: 87,88.9 88.27,87.63 88.27,81.28 88.9,80.64 91.44,80.64 92.08,80.01 92.08,50.17 91.44,49.53 v90.81,49.53 | 102.23,31.11 PL2.H | 102.23,31.11 101.6,30.48 101.6,24.13 102.23,23.49 102.03,23.49 | v101.6,43.81 107.31,43.81 107.95,43.18 107.95,31.75 107.31,31.11 102.23,31.11
N$17  (via drill 0.81 pad 1.68)
  Top 0.254: IC15. 52.7,71.75 53.34,72.39 57.15,72.39 57.78,73.03 v57.78,78.11
  Bottom 0.254: 52.07,88.9 50.8,87.63 50.8,83.19 52.07,81.92 54.61,81.92 55.24,81.28 55.24,80.01 55.88,79.38 57.15,79.38 57.78,78.74 v57.78,78.11
N$18
  Bottom 0.254: 19.68,50.8 19.68,51.44 20.32,52.07 25.4,52.07 26.67,53.34 28.37,53.34 28.57,53.34
N$19  (via drill 0.81 pad 1.68)
  Top 0.254: v40.64,75.56 32.39,75.56 31.75,76.2 v31.75,77.47
  Bottom 0.254: 45.19,74.3 43.18,74.3 41.91,75.56 v40.64,75.56 | 39.37,88.9 39.37,89.53 38.73,90.17 32.39,90.17 31.12,88.9 31.12,85.73 29.84,84.45 29.84,78.11 30.48,77.47 v31.75,77.47 31.12,77.47 | R35. 31.12,74.93 31.12,77.47 | 31.12,77.47
N$20
  Bottom 0.254: 41.91,86.36 41.91,80.64 42.55,80.01 46.99,80.01 47.62,79.38 47.62,72.39 46.99,71.75 45.19,71.75 39.37,71.75 39.37,72.39 R37.
N$21
  Bottom 0.254: 19.68,53.34 19.68,53.97 20.32,54.61 25.4,54.61 26.67,55.88 26.67,57.78 27.3,58.42 27.74,58.42 27.94,58.42
N$22
  Bottom 0.254: R36. 38.73,74.93 | R36. 39.37,74.93 39.37,74.3 40.64,73.03 45.19,73.03 | R36. 38.1,74.93 37.47,75.56 37.47,84.45 39.37,86.36
N$23  (via drill 0.81 pad 1.68)
  Top 0.254: v35.56,79.38 35.56,78.11 36.2,77.47 41.27,77.47 41.91,76.84 41.91,73.66 41.27,73.03 41.27,69.22 42.55,67.94 42.55,59.05 43.18,58.42 44.45,58.42 45.09,57.78 45.09,41.91 45.72,41.27 45.72,36.2 45.09,35.56 v45.09,24.77
  Bottom 0.254: F1. 92.71,15.88 92.08,16.51 92.08,20.95 91.44,21.59 81.28,21.59 | 81.28,21.59 74.93,21.59 74.3,20.95 72.39,20.95 72.39,24.13 71.75,24.77 v45.09,24.77 | 81.28,21.59 C2. | 36.83,86.36 36.83,85.73 35.56,84.45 v35.56,79.38
N$24
  Bottom 0.254: IC6. 55.78,62.76 56.52,63.5 56.52,64.77 55.88,65.41 49.53,65.41 48.9,66.04 48.9,76.84 51.33,76.84 51.44,76.84
N$26
  Bottom 0.254: 19.68,55.88 19.68,56.52 20.32,57.15 24.77,57.15 25.4,57.78 25.4,62.86 26.04,63.5 26.47,63.5
N$27
  Bottom 0.254: D9. 33.66,55.88 R5.
N$28
  Bottom 0.254: D2. 34.92,50.8 R4.
N$29  (via drill 0.81 pad 1.68)
  Top 0.254: 83.19,55 83.19,56.52 82.55,57.15 82.55,59.69 81.92,60.33 v78.1,60.33 | v47.62,52.07 48.9,52.07 49.53,52.7 49.53,59.05 48.9,59.69 44.45,59.69 43.81,60.33 43.81,66.67 v44.45,67.31
  Bottom 0.254: v78.1,60.33 67.31,60.33 66.67,59.69 66.67,50.8 66.04,50.17 50.16,50.17 48.9,48.89 48.9,47.62 47.62,46.36 45.09,46.36 | 49.63,52.07 v47.62,52.07 45.72,52.07 45.09,51.44 45.09,46.36 | 45.09,46.36 45.09,45.08 43.18,43.18 36.09,43.18 | v44.45,67.31 44.45,69.22 45.19,69.22 45.09,69.22
N$31
  Bottom 0.254: D3. 32.39,60.96 R6.
N$32
  Bottom 0.254: D4. 31.12,66.04 R7.
N$33
  Bottom 0.254: D5. 30.48,68.58 R8.
N$35
  Bottom 0.254: D6. 31.75,63.5 R9.
N$36  (via drill 0.81 pad 1.68)
  Top 0.254: v84.45,46.99 85.09,46.36 88.27,46.36 90.17,48.26 103.5,48.26 104.14,47.62 104.14,41.91 103.5,41.27 v102.23,41.27 101.6,41.27 100.97,41.91 98.48,41.91 98.42,41.91
  Bottom 0.254: 84.45,88.9 83.19,88.9 82.55,88.27 82.55,83.82 83.19,83.19 83.82,83.19 87,80.01 87,68.58 87.63,67.94 87.63,60.33 85.72,58.42 85.72,47.62 85.09,46.99 v84.45,46.99 | v102.23,41.27 106.05,41.27 106.68,40.64 106.68,34.29 PL2.L 101.6,33.66 100.97,33.02 100.97,28.57 100.33,27.94 100.33,21.59 100.97,20.95 102.87,20.95 103.5,21.59 103.5,25.4 104.14,26.04 110.49,26.04 111.12,25.4 111.12,23.49
N$37  (via drill 0.81 pad 1.68)
  Top 0.254: 89.78,67.94 88.27,67.94 87,66.67 v83.82,66.67 | v56.52,44.45 IC4./AS
  Bottom 0.254: v83.82,66.67 83.82,65.41 83.19,64.77 82.55,64.77 81.92,64.14 81.92,48.26 81.28,47.62 59.69,47.62 v56.52,44.45
N$38  (via drill 0.81 pad 1.68)
  Top 0.254: 89.78,57.78 v96.52,57.78
  Bottom 0.254: 92.08,88.9 93.34,87.63 93.34,85.09 93.98,84.45 93.98,58.42 94.61,57.78 v96.52,57.78
N$39  (via drill 0.81 pad 1.68)
  Top 0.254: IC3.5 95.25,56.52 96.52,55.25 v98.42,55.25
  Bottom 0.254: 94.61,88.9 96.52,88.9 97.16,88.27 97.16,85.09 97.79,84.45 100.33,84.45 100.97,83.82 | 100.97,83.82 100.97,82.55 | 100.97,83.82 100.97,70.48 97.79,67.31 97.79,65.41 99.69,63.5 99.69,55.88 99.06,55.25 v98.42,55.25
N$40  (via drill 0.81 pad 1.68)
  Top 0.254: 89.78,59.05 91.44,59.05 92.08,59.69 97.79,59.69 99.69,57.78 99.69,52.7 97.79,50.8 v96.52,50.8
  Bottom 0.254: 89.53,88.9 90.81,87.63 90.81,83.82 92.71,81.92 92.71,51.44 93.34,50.8 v96.52,50.8
N$41  (via drill 0.81 pad 1.68)
  Top 0.254: 89.78,60.33 91.44,60.33 92.71,61.59 v96.52,61.59 | v98.42,70.48 98.42,72.97
  Bottom 0.254: v96.52,61.59 95.25,61.59 94.61,62.23 94.61,69.85 95.25,70.48 v98.42,70.48
N$42  (via drill 0.81 pad 1.68)
  Top 0.254: 89.78,69.22 88.27,69.22 87.63,68.58 81.92,68.58 81.28,67.94 v81.28,66.67 | v55.88,46.99 55.24,46.36 55.24,43.81 55.88,43.18 64.01,43.18
  Bottom 0.254: v81.28,66.67 81.28,48.89 80.64,48.26 57.15,48.26 v55.88,46.99
N$43
  Bottom 0.254: 29.95,44.45 22.86,44.45 21.59,45.72 22.23,45.72
N$44  (via drill 0.81 pad 1.68)
  Top 0.254: 106.68,45.72 106.62,45.72 105.41,45.72 104.78,45.08 104.78,40 105.41,39.37 113.67,39.37 114.3,40 114.3,49.53 113.23,50.6 R24. 113.23,53.14 v112.39,53.97 112.39,59.69 PL1. 107.95,60.33 107.31,59.69 102.23,59.69 | 89.78,64.14 99.06,64.14 99.69,63.5 99.69,60.33 100.33,59.69 102.23,59.69 | 102.23,59.69 102.23,56.45
  Bottom 0.254: 111.76,66.67 112.39,66.04 v112.39,53.97
N$45  (via drill 0.81 pad 1.68)
  Top 0.254: v104.78,49.53 104.78,51.44 101.6,51.44 100.97,52.07 100.97,56.52 | v104.78,49.53 104.78,47.62 105.41,46.99 106.62,46.99 106.68,46.99 | R25. 105.41,51.44 104.78,50.8 v104.78,49.53 | 89.78,61.59 91.44,61.59 92.08,62.23 92.08,62.86 92.71,63.5 98.42,63.5 99.06,62.86 99.06,59.69 100.33,58.42 100.97,58.42 100.97,56.52 | 100.97,56.52 IC14.
  Bottom 0.254: 111.76,69.22 110.49,67.94 110.49,64.14 109.86,63.5 108.58,63.5 107.95,62.86 107.95,50.17 107.31,49.53 v104.78,49.53
N$46  (via drill 0.81 pad 1.68)
  Top 0.254: 88.27,70.72 88.27,76.2 v88.9,76.84 | 64.01,41.91 59.05,41.91 v57.15,40
  Bottom 0.254: v88.9,76.84 88.9,60.33 87,58.42 87,51.44 88.9,49.53 88.9,44.45 88.27,43.81 60.96,43.81 v57.15,40
N$47  (via drill 0.81 pad 1.68)
  Top 0.254: IC3.7 87,78.11 87.63,78.74 v90.17,78.74 | 64.01,40.64 63.5,40.64 62.87,40 v59.69,40
  Bottom 0.254: v90.17,78.74 90.81,78.11 90.81,76.2 90.17,75.56 90.17,60.33 88.27,58.42 88.27,51.44 89.53,50.17 89.53,43.18 88.9,42.55 62.23,42.55 v59.69,40
N$48  (via drill 0.81 pad 1.68)
  Top 0.254: IC4./ 78.74,31.75 79.38,31.11 v79.38,30.48 | 89.78,65.41 98.42,65.41 99.06,64.77 101.6,64.77 v102.23,65.41
  Bottom 0.254: v102.23,65.41 102.23,53.34 100.33,51.44 100.33,31.11 99.69,30.48 v79.38,30.48
N$49  (via drill 0.81 pad 1.68)
  Top 0.254: 100.97,78.17 100.97,79.38 100.33,80.01 95.89,80.01 95.25,80.64 95.25,81.28 94.61,81.92 v90.17,81.92
  Bottom 0.254: 89.53,86.36 89.53,82.55 v90.17,81.92
N$50  (via drill 0.81 pad 1.68)
  Top 0.254: v96.52,68.58 96.52,71.12 97.16,71.75 IC7. | v41.91,31.75 41.91,37.47 40.64,38.73 40.64,44.45 v41.91,45.72 | v76.84,33.02 74.3,33.02 v76.84,33.02
  Bottom 0.254: v41.91,31.75 52.7,31.75 53.98,33.02 v76.84,33.02 77.47,33.66 95.89,33.66 96.52,34.29 96.52,40.64 95.89,41.27 93.98,41.27 93.34,41.91 93.34,46.99 93.98,47.62 97.16,47.62 97.79,48.26 97.79,53.97 97.16,54.61 97.16,55.88 98.42,57.15 98.42,63.5 96.52,65.41 v96.52,68.58 | 36.09,45.72 37.47,45.72 38.1,46.36 41.27,46.36 v41.91,45.72
N$51  (via drill 0.81 pad 1.68)
  Top 0.254: IC4.L2 63.5,35.56 62.87,34.92 v60.96,34.92 | 88.27,35.56 88.27,37.47 87.63,38.1 Q1. | 89.53,35.23 88.59,35.23 88.27,35.56 | 88.27,35.56 88.27,38.73 90.81,38.73 91.44,38.1 v91.44,37.47
  Bottom 0.254: v60.96,34.92 90.81,34.92 91.44,35.56 v91.44,37.47
N$52  (via drill 0.81 pad 1.68)
  Top 0.254: v58.42,34.92 58.42,36.2 59.05,36.83 IC4.L1 | 81.92,35.23 82.86,35.23 83.19,35.56 | 83.44,38.1 83.19,38.1 83.19,35.56 | 83.19,35.56 83.19,38.73 81.28,38.73 80.64,38.1 v80.64,37.47
  Bottom 0.254: v58.42,34.92 58.42,36.2 59.05,36.83 61.59,36.83 62.23,36.2 80.01,36.2 80.64,36.83 v80.64,37.47
N$53
  Bottom 0.254: 19.05,80.64 19.05,79.38 19.68,78.74 21.59,78.74 21.57,78.77 T1.
N$54  (via drill 0.81 pad 1.68)
  Top 0.254: 78.1,70.72 78.1,73.03 79.38,74.3 79.38,80.01 78.74,80.64 76.2,80.64 75.56,81.28 75.56,82.55 74.3,83.82 73.03,83.82 71.75,85.09 63.5,85.09 62.23,83.82 47.62,83.82 46.99,83.19 v46.99,81.92
  Bottom 0.254: v46.99,81.92 46.99,86.36
N$55
  Top 0.254: 74.3,35.56 78.1,35.56 78.74,36.2 78.74,38.1 81.28,40.64 93.28,40.64
N$56  (via drill 0.81 pad 1.68)
  Top 0.254: 76.84,70.72 76.84,73.03 78.74,74.93 78.74,79.38 78.1,80.01 75.56,80.01 74.93,80.64 74.93,81.28 74.3,81.92 v73.66,81.92
  Bottom 0.254: 46.99,88.9 46.99,90.17 47.62,90.81 71.75,90.81 72.39,90.17 72.39,82.55 73.03,81.92 v73.66,81.92
N$57  (via drill 0.81 pad 1.68)
  Top 0.254: 74.06,69.22 71.75,69.22 71.12,69.85 71.12,81.92 v69.85,83.19
  Bottom 0.254: 49.53,88.9 49.53,89.53 50.16,90.17 69.22,90.17 69.85,89.53 v69.85,83.19
N$58  (via drill 0.81 pad 1.68)
  Top 0.254: 74.06,67.94 70.48,67.94 69.85,68.58 v69.85,80.64
  Bottom 0.254: 52.07,86.36 52.07,84.45 52.7,83.82 60.96,83.82 61.59,83.19 61.59,81.28 62.23,80.64 v69.85,80.64
N$59  (via drill 0.81 pad 1.68)
  Top 0.254: 75.56,70.48 75.56,70.72 75.56,71.12 72.39,71.12 71.75,71.75 71.75,83.82 71.12,84.45 64.13,84.45 62.87,83.19 50.16,83.19 49.53,82.55 v49.53,81.92
  Bottom 0.254: v49.53,81.92 49.53,86.36
N$60  (via drill 0.81 pad 1.68)
  Top 0.254: 74.06,66.67 69.85,66.67 69.22,67.31 69.22,78.11 67.94,79.38 67.94,83.19 67.31,83.82 64.77,83.82 63.5,82.55 52.7,82.55 50.8,80.64 46.36,80.64 45.72,81.28 45.72,83.82 45.09,84.45 24.13,84.45 23.5,83.82 v23.5,83.19
  Bottom 0.254: R1. 26.67,82.55 26.04,83.19 v23.5,83.19
N$61  (via drill 0.81 pad 1.68)
  Top 0.254: v26.67,71.75 26.67,55.25 26.04,54.61 26.04,26.67 v26.67,26.04
  Bottom 0.254: 106.05,18.41 97.16,18.41 96.52,19.05 96.52,20.95 96.52,25.4 95.89,26.04 v26.67,26.04 | 19.68,63.5 19.68,69.22 20.32,69.85 22.86,69.85 24.77,71.75 v26.67,71.75
N$63
  Top 0.254: 98.48,44.45 96.52,44.45 96.52,30.48 94.61,28.57 94.61,27.3 | SJ1. 94.49,27.18 94.61,27.3 | 94.41,27.3 94.61,27.3
N$64
  Bottom 0.254: D7. 33.02,58.42 R10.
N$65
  Bottom 0.254: R3. JP3.
  Bottom 0.406: R3. 104.78,23.49
N$67
  Bottom 0.254: D8. 33.66,53.34 R11.
N$68  (via drill 0.81 pad 1.68)
  Top 0.254: v40,53.34 36.83,53.34 36.2,52.7 36.2,45.08 35.56,44.45 33.02,44.45 32.39,43.81 32.39,42.61 32.39,42.55
  Bottom 0.254: 38.58,55.25 37.95,55.88 38.1,55.88 38.1,54.61 39.37,54.61 40,53.97 v40,53.34
N$70  (via drill 0.81 pad 1.68)
  Top 0.254: IC3.L1 84.45,77.47 83.82,78.11 v82.55,78.11 | 39.37,20.62 39.37,20.95 43.18,20.95 | 43.18,20.95 Q2. | 43.18,20.95 47.62,20.95 49.53,22.86 v49.53,46.36
  Bottom 0.254: v82.55,78.11 81.92,78.11 79.38,75.56 79.38,66.04 80.64,64.77 80.64,49.53 80.01,48.89 53.34,48.89 52.7,48.26 52.7,46.99 52.07,46.36 v49.53,46.36
N$71  (via drill 0.81 pad 1.68)
  Top 0.254: v40,60.96 38.1,60.96 37.47,60.33 37.47,57.78 36.83,57.15 34.92,57.15 34.92,55.94
  Bottom 0.254: v40,60.96 36.68,60.96
N$72  (via drill 0.81 pad 1.68)
  Top 0.254: 32.39,55.94 32.39,57.78 33.02,58.42 36.2,58.42 36.83,59.05 36.83,65.41 37.47,66.04 v40,66.04
  Bottom 0.254: v40,66.04 35.41,66.04
N$73  (via drill 0.81 pad 1.68)
  Top 0.254: 34.92,69.28 34.92,71.75 34.29,72.39 v33.66,72.39
  Bottom 0.254: 34.77,68.58 34.92,68.58 34.92,71.75 34.29,72.39 v33.66,72.39
N$74  (via drill 0.81 pad 1.68)
  Top 0.254: 32.39,69.28 32.39,70.48 31.12,71.75 31.12,73.66 31.75,74.3 38.1,74.3 38.73,73.66 38.73,68.58 39.37,67.94 41.27,67.94 41.91,67.31 41.91,64.14 41.27,63.5 v40,63.5
  Bottom 0.254: 36.04,63.5 v40,63.5
N$75  (via drill 0.81 pad 1.68)
  Top 0.254: 34.92,26.09 34.92,27.94 35.56,28.57 43.81,28.57 44.45,29.21 44.45,36.2 45.09,36.83 45.09,40.64 44.45,41.27 44.45,57.15 43.81,57.78 40.64,57.78 v40,58.42
  Bottom 0.254: v40,58.42 37.31,58.42
N$76  (via drill 0.81 pad 1.68)
  Top 0.254: 34.92,37.41 34.92,36.83 v40,36.83 | v53.98,38.73 52.7,40 52.7,45.72 53.34,46.36 53.34,64.77 53.98,65.41 v59.69,65.41
  Bottom 0.254: R12. 38.73,33.02 40,34.29 v40,36.83 40,38.1 42.55,40.64 50.8,40.64 52.7,38.73 v53.98,38.73 | 55.78,58.42 57.15,58.42 58.42,59.69 58.42,64.14 v59.69,65.41
N$77  (via drill 0.81 pad 1.68)
  Top 0.254: v41.91,52.07 42.55,52.07 43.18,51.44 43.18,44.45 41.91,43.18 41.91,38.73 42.55,38.1 42.55,33.66 43.18,33.02 43.18,29.84 42.55,29.21 33.02,29.21 32.39,28.57 32.39,26.09 32.39,26.04
  Bottom 0.254: v41.91,52.07 38.1,52.07 38.1,52.7 37.95,52.86 37.95,53.34
N$78
  Bottom 0.254: 45.72,75.56 45.19,75.56 43.81,75.56 41.91,77.47 R23. 38.73,77.47 38.73,83.82 40.64,85.73 40.64,87.63 41.91,88.9
N$79  (via drill 0.81 pad 1.68)
  Top 0.254: 88.27,55 94.86,55 v96.52,53.34
  Bottom 0.254: 92.08,86.36 92.08,84.45 93.34,83.19 93.34,53.97 93.98,53.34 v96.52,53.34
N$80  (via drill 0.81 pad 1.68)
  Top 0.254: 32.39,37.41 32.39,35.56 33.02,34.92 v33.02,31.75 | v53.98,41.27 53.98,62.23 54.61,62.86 v59.69,62.86
  Bottom 0.254: R13. 35.56,31.75 v33.02,31.75 36.2,31.75 38.73,34.29 38.73,38.1 41.91,41.27 v53.98,41.27 | 55.78,57.15 57.15,57.15 59.05,59.05 59.05,62.23 v59.69,62.86
N$81
  Bottom 0.254: 23.24,79.73 23.24,79.63 23.5,79.38 24.13,79.38 24.77,78.74 24.77,77.47 25.4,76.84 26.04,76.84 26.67,77.47 26.67,77.27
N$82  (via drill 0.81 pad 1.68)
  Top 0.254: v41.27,49.53 38.1,49.53 37.47,48.89 37.47,43.81 36.83,43.18 34.92,43.18 34.92,42.61 34.92,42.55
  Bottom 0.254: v41.27,49.53 41.27,50.17 40.64,50.8 39.22,50.8
N$83  (via drill 0.81 pad 1.68)
  Top 0.254: 34.92,50.74 34.92,53.34 37.47,55.88 v40,55.88
  Bottom 0.254: 55.88,55.88 55.78,55.88 53.98,55.88 53.34,56.52 53.34,64.14 | R14. 54.61,64.14 53.34,64.14 | 53.34,64.14 52.7,64.77 42.55,64.77 41.91,64.14 41.91,57.78 v40,55.88
N$85  (via drill 0.81 pad 1.68)
  Top 0.254: 32.39,50.74 32.39,49.53 31.75,48.89 27.94,48.89 v27.3,49.53
  Bottom 0.254: 66.67,64.14 R15. 66.67,62.86 66.04,62.23 61.59,62.23 60.96,61.59 60.96,59.69 57.78,56.52 57.78,54.61 55.78,54.61 52.7,54.61 52.7,63.5 52.07,64.14 43.18,64.14 42.55,63.5 42.55,57.15 41.91,56.52 41.91,54.61 43.18,53.34 43.18,48.89 42.55,48.26 28.57,48.26 v27.3,49.53
N$87  (via drill 0.81 pad 1.68)
  Top 0.254: 34.92,64.08 34.92,66.67 36.83,68.58 v36.83,69.85 | v46.36,29.84 v46.36,50.17 | v46.99,54.61 46.36,55.25 46.36,58.42 45.72,59.05 43.81,59.05 43.18,59.69 43.18,69.22 v42.55,69.85
  Bottom 0.254: v46.36,50.17 47.62,50.17 48.26,50.8 50.8,50.8 51.44,51.44 51.44,53.97 50.8,54.61 49.63,54.61 v46.99,54.61 | R16. 51.23,37.03 52.07,36.2 52.07,33.02 51.44,32.38 43.18,32.38 42.55,33.02 41.27,33.02 40.64,32.38 40.64,29.84 41.27,29.21 45.72,29.21 v46.36,29.84 | v42.55,69.85 v36.83,69.85
N$89  (via drill 0.81 pad 1.68)
  Top 0.254: 32.39,64.08 32.39,60.33 33.02,59.69 35.56,59.69 36.2,60.33 36.2,66.67 36.83,67.31 40.64,67.31 41.27,66.67 41.27,65.41 40.64,64.77 39.37,64.77 38.73,64.14 38.73,62.86 39.37,62.23 40.64,62.23 41.27,61.59 41.27,60.33 40.64,59.69 39.37,59.69 38.73,59.05 38.73,57.78 39.37,57.15 42.55,57.15 43.18,56.52 v43.18,55.88 43.81,55.25 v43.81,38.73
  Bottom 0.254: v43.18,55.88 49.63,55.88 | R17. v43.81,38.73
N$90
  Bottom 0.254: 22.23,43.18 29.95,43.18 30.48,43.18
N$91  (via drill 0.81 pad 1.68)
  Top 0.254: 34.92,20.32 34.92,20.89 34.92,22.23 35.56,22.86 46.99,22.86 47.62,23.49 v47.62,38.73 47.62,48.89 50.16,51.44 50.16,60.33 49.53,60.96 45.72,60.96 v45.09,61.59
  Bottom 0.254: 49.63,57.15 45.72,57.15 45.09,57.78 v45.09,61.59 | R18. 46.99,38.1 v47.62,38.73
N$92
  Bottom 0.254: 22.23,40.64 24.13,40.64 25.4,41.91 29.95,41.91 30.48,41.91
N$93  (via drill 0.81 pad 1.68)
  Top 0.254: 32.39,20.89 32.39,17.14 33.02,16.51 v33.66,16.51 36.2,16.51 36.83,17.14 36.83,21.59 37.47,22.23 47.62,22.23 48.26,22.86 48.26,36.83 48.9,37.47 48.9,40 48.26,40.64 48.26,48.26 50.8,50.8 50.8,60.96 50.16,61.59 47.62,61.59 46.99,62.23 v46.99,62.86
  Bottom 0.254: 49.63,58.42 47.62,58.42 46.99,59.05 v46.99,62.86 | R19. 27.94,17.14 28.57,16.51 v33.66,16.51
N$94
  Bottom 0.254: 29.95,40.64 26.67,40.64 24.77,38.73 20.32,38.73 19.68,39.37 19.68,40.64
N$95
  Bottom 0.254: 19.68,43.18 19.05,43.18 18.41,42.55 18.41,38.1 19.05,37.47 26.04,37.47 27.94,39.37 29.95,39.37
N$96  (via drill 0.81 pad 1.68)
  Top 0.254: v99.69,66.67 89.78,66.67 | v99.69,66.67 89.78,66.67 | v99.69,66.67 89.78,66.67 | v99.69,66.67 89.78,66.67 | v93.34,49.53 v99.06,49.53 | 51.49,74.3 55.24,74.3 55.88,74.93 55.88,78.74 56.52,79.38 59.05,79.38 59.69,78.74 59.69,69.85 60.33,69.22 62.23,69.22 62.87,68.58 62.87,61.59 62.23,60.96 61.59,60.96 60.33,59.69 60.33,53.97 59.69,53.34 55.24,53.34 54.61,52.7 54.61,43.18 55.88,41.91 55.88,38.1 v53.98,36.2
  Bottom 0.254: v99.06,49.53 99.06,52.07 100.97,53.97 100.97,64.14 99.69,65.41 v99.69,66.67 | v93.34,49.53 91.44,47.62 90.81,47.62 90.17,46.99 90.17,41.91 89.53,41.27 64.77,41.27 61.59,38.1 55.88,38.1 v53.98,36.2
N$97
  Bottom 0.254: 19.68,45.72 18.41,45.72 17.78,45.08 17.78,36.83 18.41,36.2 27.3,36.2 29.21,38.1 29.95,38.1
N$98  (via drill 0.81 pad 1.68)
  Top 0.254: v87,48.89 87,55
  Bottom 0.254: v87,48.89 87,45.72 86.36,45.08 60.96,45.08 58.42,42.55 55.24,42.55 54.61,43.18 45.72,43.18 44.45,41.91 41.27,41.91 39.37,40 38.1,40 37.47,40.64 36.09,40.64
N$99  (via drill 0.81 pad 1.68)
  Top 0.254: v27.3,31.11 v27.3,46.99
  Bottom 0.254: 19.68,48.26 19.68,48.89 20.32,49.53 23.5,49.53 26.04,46.99 v27.3,46.99 | 36.09,39.37 37.47,39.37 38.1,38.73 38.1,35.56 36.2,33.66 27.94,33.66 27.3,33.02 v27.3,31.11
N$100  (via drill 0.81 pad 1.68)
  Top 0.254: v67.94,58.42 67.94,72.39 67.31,73.03 v64.13,73.03
  Bottom 0.254: 67.94,55.88 R20. | 67.94,52.7 67.94,55.88 | 67.94,55.88 v67.94,58.42 | v64.13,73.03 54.61,73.03 53.34,74.3 51.33,74.3
N$101  (via drill 0.81 pad 1.68)
  Top 0.254: v63.5,57.78 65.41,57.78 66.04,58.42 v66.04,71.12
  Bottom 0.254: 62.23,55.25 62.23,57.78 | 61.59,59.69 62.23,60.33 R21. 61.59,60.33 61.59,58.42 62.23,57.78 | 62.23,57.78 v63.5,57.78 | v66.04,71.12 66.04,74.3 65.41,74.93 53.98,74.93 53.34,75.56 51.33,75.56
N$102
  Top 0.254: 76.84,55.25 IC3.2 76.84,43.18 | 76.84,43.18 74.3,43.18 | 76.84,43.18 71.12,43.18 70.48,42.55 70.48,27.3 69.22,26.04 69.42,26.04
N$104
  Top 0.254: 76.2,44.45 76.2,49.53 75.56,50.17 IC3.3 | 76.2,44.45 74.3,44.45 | 76.2,44.45 70.48,44.45 69.85,43.81 69.85,27.94 62.23,27.94 61.59,27.3 61.59,26.04 61.39,26.04
N$105
  Top 0.254: IC3.4 74.3,56.52 74.3,50.17 75.56,48.89 75.56,45.72 | 75.56,45.72 74.3,45.72 | 75.56,45.72 69.85,45.72 69.22,45.08 69.22,28.57 59.69,28.57 59.05,27.94 59.05,28.14
N$106
  Top 0.254: 60.96,47.42 60.96,46.99 64.01,46.99 67.94,46.99 71.12,50.17 71.12,58.42 71.75,59.05 IC3.6
N$107  (via drill 0.81 pad 1.68)
  Top 0.254: v77.47,82.55 79.38,82.55 80.01,81.92 80.01,73.66 79.38,73.03 IC3.1 | 46.3,75.56 48.26,75.56 48.26,80.01 | 48.26,80.01 45.72,80.01 45.09,80.64 45.09,83.19 44.45,83.82 27.94,83.82 25.4,81.28 21.59,81.28 20.95,81.92 19.68,81.92 19.05,82.55 v19.05,83.19 | 48.26,80.01 51.44,80.01 52.7,81.28 v57.15,81.28
  Bottom 0.254: v57.15,81.28 59.05,81.28 59.69,80.64 59.69,80.01 60.33,79.38 71.75,79.38 72.39,80.01 76.84,80.01 77.47,80.64 v77.47,82.55 | 43.81,90.81 29.84,90.81 | 44.45,88.9 44.45,90.17 43.81,90.81 | 43.81,90.81 25.4,90.81 24.77,90.17 24.77,87.63 20.32,83.19 v19.05,83.19
N$108
  Bottom 0.254: 19.68,58.42 20.95,59.69 23.5,59.69 24.13,60.33 24.13,67.94 24.77,68.58 25.2,68.58 25.4,68.58
N$109
  Bottom 0.254: 29.84,50.8 29.64,50.8 29.21,50.8 28.57,51.44 26.67,51.44 26.04,50.8 22.23,50.8
N$110
  Bottom 0.254: 22.23,53.34 25.4,53.34 27.94,55.88 28.37,55.88 28.57,55.88
N$111
  Bottom 0.254: 22.23,55.88 25.4,55.88 26.04,56.52 26.04,60.33 26.67,60.96 27.1,60.96
N$112
  Bottom 0.254: 22.23,58.42 24.13,58.42 24.77,59.05 24.77,65.41 25.4,66.04 25.83,66.04 26.04,66.04

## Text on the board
text: I2C | CAN | HSTG | V1_0 | C2002 | + | 12V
